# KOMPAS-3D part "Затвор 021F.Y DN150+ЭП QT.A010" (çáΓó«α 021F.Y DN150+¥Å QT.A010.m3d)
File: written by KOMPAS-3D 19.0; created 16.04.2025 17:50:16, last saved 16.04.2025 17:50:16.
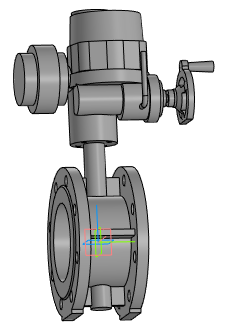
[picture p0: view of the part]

Document properties: Полное имя файла: Затвор 021F.Y DN150+ЭП QT.A010.a3d

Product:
- Part/product: Затвор 021F.Y DN150+ЭП QT.A010
    Масса: 60.4766

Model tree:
1. Операция без истории:1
